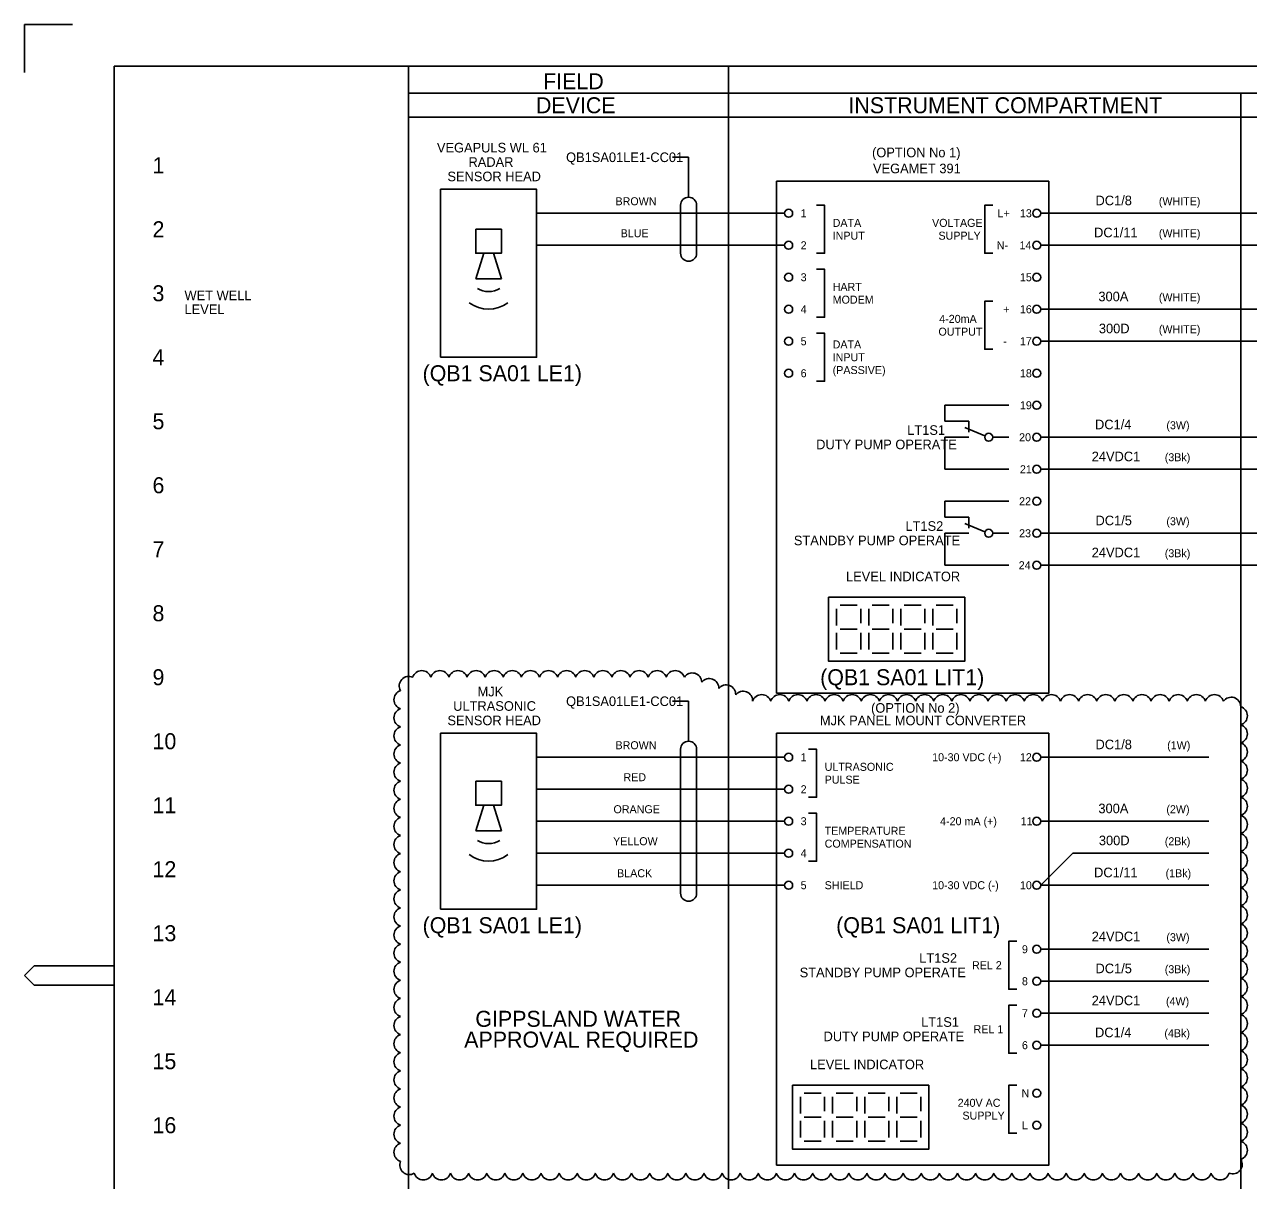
# Model space of a CAD drawing. Extents: x 0 to 841, y 0 to 594.
# Drawn here: x 0 to 382.4, y 232.7 to 594 of the extents above; entities that cross this region are included whole.
import ezdxf

# ---------------------------------------------------------------- set-up
doc = ezdxf.new("R2010")
doc.units = 0
for name, color, linetype in [('A1BORDER', 7, 'Continuous'), ('BASE', 7, 'Continuous'), ('Level 1', 7, 'Continuous'), ('Level 10', 7, 'Continuous'), ('Level 2', 7, 'Continuous'), ('Level 3', 7, 'Continuous')]:
    doc.layers.add(name, color=color, linetype=linetype)

msp = doc.modelspace()

# ---------------------------------------------------------------- linework, layer by layer
at = {"layer": 'A1BORDER'}
for p, q in [((0, 594), (15, 594)), ((0, 579), (0, 594)), ((28, 581), (829, 581)), ((28, 581), (28, 15)), ((3, 299.76), (0, 296.76)), ((28, 299.76), (3, 299.76)), ((3, 293.76), (0, 296.76)), ((28, 293.76), (3, 293.76))]:
    msp.add_line(p, q, dxfattribs=at)
at = {"layer": 'BASE'}
for p, q in [((317.5, 535), (760, 535)), ((317.5, 525), (760, 525)), ((317.5, 505), (630, 505)), ((317.5, 495), (580, 495))]:
    msp.add_line(p, q, dxfattribs=at)
at = {"layer": 'Level 1'}
for p, q in [((120, 57.5), (120, 581)), ((220, 57.5), (220, 581)), ((120, 572.5), (829, 572.5)), ((380, 57), (380, 572.5)), ((120, 565), (829, 565)), ((207.5, 552.5), (202.5, 552.5)), ((207.5, 552.5), (207.5, 540)), ((205, 537.5), (205, 522.5)), ((210, 537.5), (210, 522.5)), ((237.5, 535), (160, 535)), ((237.5, 535), (237.5, 535)), ((240, 535), (240, 535)), ((315, 535), (315, 535)), ((317.5, 535), (317.5, 535)), ((237.5, 525), (160, 525)), ((237.5, 525), (237.5, 525)), ((240, 525), (240, 525)), ((315, 525), (315, 525)), ((317.5, 525), (317.5, 525)), ((237.5, 515), (237.5, 515)), ((240, 515), (240, 515)), ((315, 515), (315, 515)), ((317.5, 515), (317.5, 515)), ((237.5, 505), (237.5, 505)), ((240, 505), (240, 505)), ((315, 505), (315, 505)), ((317.5, 505), (317.5, 505)), ((237.5, 495), (237.5, 495)), ((240, 495), (240, 495)), ((315, 495), (315, 495)), ((317.5, 495), (317.5, 495)), ((237.5, 485), (237.5, 485)), ((240, 485), (240, 485)), ((315, 485), (315, 485)), ((317.5, 485), (317.5, 485)), ((287.5, 470), (287.5, 475)), ((287.5, 475), (307.5, 475)), ((315, 475), (315, 475)), ((317.5, 475), (317.5, 475)), ((287.5, 470), (292.5, 470)), ((287.5, 455), (287.5, 465)), ((287.5, 465), (292.5, 465)), ((292.5, 465), (292.5, 465)), ((302.5, 465), (302.5, 465)), ((302.5, 465), (307.5, 465)), ((315, 465), (315, 465)), ((317.5, 465), (317.5, 465)), ((760, 465), (317.5, 465)), ((307.5, 455), (287.5, 455)), ((315, 455), (315, 455)), ((317.5, 455), (317.5, 455)), ((760, 455), (317.5, 455)), ((287.5, 440), (287.5, 445)), ((287.5, 445), (307.5, 445)), ((315, 445), (315, 445)), ((317.5, 445), (317.5, 445)), ((287.5, 440), (292.5, 440)), ((287.5, 425), (287.5, 435)), ((287.5, 435), (292.5, 435)), ((292.5, 435), (292.5, 435)), ((302.5, 435), (302.5, 435)), ((302.5, 435), (307.5, 435)), ((315, 435), (315, 435)), ((317.5, 435), (317.5, 435)), ((760, 435), (317.5, 435)), ((307.5, 425), (287.5, 425)), ((315, 425), (315, 425)), ((317.5, 425), (317.5, 425)), ((760, 425), (317.5, 425)), ((207.5, 382.5), (202.5, 382.5)), ((207.5, 382.5), (207.5, 370)), ((205, 367.5), (205, 322.5)), ((210, 367.5), (210, 322.5)), ((237.5, 365), (160, 365)), ((237.5, 365), (237.5, 365)), ((240, 365), (240, 365)), ((315, 365), (315, 365)), ((317.5, 365), (317.5, 365)), ((370, 365), (317.5, 365)), ((237.5, 355), (160, 355)), ((237.5, 355), (237.5, 355)), ((240, 355), (240, 355)), ((237.5, 345), (160, 345)), ((237.5, 345), (237.5, 345)), ((240, 345), (240, 345)), ((315, 345), (315, 345)), ((317.5, 345), (317.5, 345)), ((370, 345), (317.5, 345)), ((237.5, 335), (160, 335)), ((237.5, 335), (237.5, 335)), ((240, 335), (240, 335)), ((317.5, 325), (327.5, 335)), ((370, 335), (327.5, 335)), ((237.5, 325), (160, 325)), ((237.5, 325), (237.5, 325)), ((240, 325), (240, 325)), ((315, 325), (315, 325)), ((317.5, 325), (317.5, 325)), ((370, 325), (317.5, 325)), ((315, 305), (315, 305)), ((317.5, 305), (317.5, 305)), ((370, 305), (317.5, 305)), ((315, 295), (315, 295)), ((317.5, 295), (317.5, 295)), ((370, 295), (317.5, 295)), ((315, 285), (315, 285)), ((317.5, 285), (317.5, 285)), ((370, 285), (317.5, 285)), ((315, 275), (315, 275)), ((317.5, 275), (317.5, 275)), ((370, 275), (317.5, 275)), ((315, 260), (315, 260)), ((317.5, 260), (317.5, 260)), ((315, 250), (315, 250)), ((317.5, 250), (317.5, 250))]:
    msp.add_line(p, q, dxfattribs=at)
for points in [[(235, 385), (235, 545), (320, 545), (320, 385)], [(130, 490), (130, 542.5), (160, 542.5), (160, 490)], [(251.25, 415), (293.75, 415), (293.75, 395), (251.25, 395)], [(130, 317.5), (130, 372.5), (160, 372.5), (160, 317.5)], [(235, 237.5), (235, 372.5), (320, 372.5), (320, 237.5)], [(240, 262.5), (282.5, 262.5), (282.5, 242.5), (240, 242.5)]]:
    msp.add_lwpolyline(points, close=True, dxfattribs=at)
for points in [[(247.5, 522.5), (250, 522.5), (250, 537.5), (247.5, 537.5)], [(302.5, 522.5), (300, 522.5), (300, 537.5), (302.5, 537.5)], [(247.5, 502.5), (250, 502.5), (250, 517.5), (247.5, 517.5)], [(302.5, 492.5), (300, 492.5), (300, 507.5), (302.5, 507.5)], [(247.5, 482.5), (250, 482.5), (250, 497.5), (247.5, 497.5)], [(245, 352.5), (247.5, 352.5), (247.5, 367.5), (245, 367.5)], [(245, 332.5), (247.5, 332.5), (247.5, 347.5), (245, 347.5)], [(310, 292.5), (307.5, 292.5), (307.5, 307.5), (310, 307.5)], [(310, 272.5), (307.5, 272.5), (307.5, 287.5), (310, 287.5)], [(310, 247.5), (307.5, 247.5), (307.5, 262.5), (310, 262.5)]]:
    msp.add_lwpolyline(points, dxfattribs=at)
for centre, radius, start, end in [((207.5, 537.5), 2.5, 0, 180), ((207.5, 522.5), 2.5, 180, 0), ((120.06, 387.3), 2.97, 65.3442, 210.3442), ((124.13, 389.11), 2.97, 17.5, 162.5), ((129.78, 389.11), 2.97, 17.5, 162.5), ((135.44, 389.11), 2.97, 17.5, 162.5), ((141.1, 389.11), 2.97, 17.5, 162.5), ((146.76, 389.11), 2.97, 17.5, 162.5), ((152.41, 389.11), 2.97, 17.5, 162.5), ((158.07, 389.11), 2.97, 17.5, 162.5), ((163.73, 389.11), 2.97, 17.5, 162.5), ((169.39, 389.11), 2.97, 17.5, 162.5), ((175.05, 389.11), 2.97, 17.5, 162.5), ((180.7, 389.11), 2.97, 17.5, 162.5), ((186.36, 389.11), 2.97, 17.5, 162.5), ((192.02, 389.11), 2.97, 17.5, 162.5), ((197.68, 389.11), 2.97, 17.5, 162.5), ((203.33, 389.11), 2.97, 17.5, 162.5), ((208.64, 388.37), 2.97, 1.7022, 146.7022), ((213.94, 386.63), 2.97, 356.944, 141.944), ((219.24, 384.64), 2.97, 356.944, 141.944), ((118.39, 382.98), 2.97, 107.5, 252.5), ((224.54, 382.66), 2.97, 356.944, 141.944), ((230.33, 381.61), 2.97, 17.5, 162.5), ((235.99, 381.61), 2.97, 17.5, 162.5), ((241.64, 381.61), 2.97, 17.5, 162.5), ((247.3, 381.61), 2.97, 17.5, 162.5), ((252.96, 381.61), 2.97, 17.5, 162.5), ((258.62, 381.61), 2.97, 17.5, 162.5), ((264.28, 381.61), 2.97, 17.5, 162.5), ((269.93, 381.61), 2.97, 17.5, 162.5), ((275.59, 381.61), 2.97, 17.5, 162.5), ((281.25, 381.61), 2.97, 17.5, 162.5), ((286.91, 381.61), 2.97, 17.5, 162.5), ((292.56, 381.61), 2.97, 17.5, 162.5), ((298.22, 381.61), 2.97, 17.5, 162.5), ((303.88, 381.61), 2.97, 17.5, 162.5), ((309.54, 381.61), 2.97, 17.5, 162.5), ((315.2, 381.61), 2.97, 17.5, 162.5), ((320.85, 381.61), 2.97, 17.5, 162.5), ((326.51, 381.61), 2.97, 17.5, 162.5), ((332.17, 381.61), 2.97, 17.5, 162.5), ((337.83, 381.61), 2.97, 17.5, 162.5), ((343.48, 381.61), 2.97, 17.5, 162.5), ((349.14, 381.61), 2.97, 17.5, 162.5), ((354.8, 381.61), 2.97, 17.5, 162.5), ((360.46, 381.61), 2.97, 17.5, 162.5), ((366.12, 381.61), 2.97, 17.5, 162.5), ((371.77, 381.61), 2.97, 17.5, 162.5), ((377.03, 380.79), 2.97, 359.904, 144.904), ((118.39, 377.32), 2.97, 107.5, 252.5), ((379.11, 377.96), 2.97, 287.5, 72.5), ((379.11, 372.3), 2.97, 287.5, 72.5), ((118.39, 371.66), 2.97, 107.5, 252.5), ((118.39, 366), 2.97, 107.5, 252.5), ((207.5, 367.5), 2.5, 0, 180), ((379.11, 366.64), 2.97, 287.5, 72.5), ((379.11, 360.98), 2.97, 287.5, 72.5), ((118.39, 360.35), 2.97, 107.5, 252.5), ((118.39, 354.69), 2.97, 107.5, 252.5), ((379.11, 355.33), 2.97, 287.5, 72.5), ((118.39, 349.03), 2.97, 107.5, 252.5), ((379.11, 349.67), 2.97, 287.5, 72.5), ((118.39, 343.37), 2.97, 107.5, 252.5), ((379.11, 344.01), 2.97, 287.5, 72.5), ((118.39, 337.72), 2.97, 107.5, 252.5), ((379.11, 338.35), 2.97, 287.5, 72.5), ((118.39, 332.06), 2.97, 107.5, 252.5), ((379.11, 332.7), 2.97, 287.5, 72.5), ((118.39, 326.4), 2.97, 107.5, 252.5), ((379.11, 327.04), 2.97, 287.5, 72.5), ((118.39, 320.74), 2.97, 107.5, 252.5), ((207.5, 322.5), 2.5, 180, 0), ((379.11, 321.38), 2.97, 287.5, 72.5), ((118.39, 315.08), 2.97, 107.5, 252.5), ((379.11, 315.72), 2.97, 287.5, 72.5), ((118.39, 309.43), 2.97, 107.5, 252.5), ((379.11, 310.06), 2.97, 287.5, 72.5), ((118.39, 303.77), 2.97, 107.5, 252.5), ((379.11, 304.41), 2.97, 287.5, 72.5), ((118.39, 298.11), 2.97, 107.5, 252.5), ((379.11, 298.75), 2.97, 287.5, 72.5), ((118.39, 292.45), 2.97, 107.5, 252.5), ((379.11, 293.09), 2.97, 287.5, 72.5), ((118.39, 286.8), 2.97, 107.5, 252.5), ((379.11, 287.43), 2.97, 287.5, 72.5), ((118.39, 281.14), 2.97, 107.5, 252.5), ((379.11, 281.78), 2.97, 287.5, 72.5), ((118.39, 275.48), 2.97, 107.5, 252.5), ((379.11, 276.12), 2.97, 287.5, 72.5), ((118.39, 269.82), 2.97, 107.5, 252.5), ((379.11, 270.46), 2.97, 287.5, 72.5), ((118.39, 264.16), 2.97, 107.5, 252.5), ((379.11, 264.8), 2.97, 287.5, 72.5), ((118.39, 258.51), 2.97, 107.5, 252.5), ((379.11, 259.14), 2.97, 287.5, 72.5), ((379.11, 253.49), 2.97, 287.5, 72.5), ((118.39, 252.85), 2.97, 107.5, 252.5), ((118.39, 247.19), 2.97, 107.5, 252.5), ((379.11, 247.83), 2.97, 287.5, 72.5), ((379.11, 242.17), 2.97, 287.5, 72.5), ((118.39, 241.53), 2.97, 107.5, 252.5), ((120.22, 237.53), 2.97, 156.6035, 301.6035), ((377.5, 237.74), 2.96, 247.6624, 32.6624), ((124.61, 235.89), 2.97, 197.5, 342.5), ((130.26, 235.89), 2.97, 197.5, 342.5), ((135.92, 235.89), 2.97, 197.5, 342.5), ((141.58, 235.89), 2.97, 197.5, 342.5), ((147.24, 235.89), 2.97, 197.5, 342.5), ((152.89, 235.89), 2.97, 197.5, 342.5), ((158.55, 235.89), 2.97, 197.5, 342.5), ((164.21, 235.89), 2.97, 197.5, 342.5), ((169.87, 235.89), 2.97, 197.5, 342.5), ((175.53, 235.89), 2.97, 197.5, 342.5), ((181.18, 235.89), 2.97, 197.5, 342.5), ((186.84, 235.89), 2.97, 197.5, 342.5), ((192.5, 235.89), 2.97, 197.5, 342.5), ((198.16, 235.89), 2.97, 197.5, 342.5), ((203.81, 235.89), 2.97, 197.5, 342.5), ((209.47, 235.89), 2.97, 197.5, 342.5), ((215.13, 235.89), 2.97, 197.5, 342.5), ((220.79, 235.89), 2.97, 197.5, 342.5), ((226.45, 235.89), 2.97, 197.5, 342.5), ((232.1, 235.89), 2.97, 197.5, 342.5), ((237.76, 235.89), 2.97, 197.5, 342.5), ((243.42, 235.89), 2.97, 197.5, 342.5), ((249.08, 235.89), 2.97, 197.5, 342.5), ((254.73, 235.89), 2.97, 197.5, 342.5), ((260.39, 235.89), 2.97, 197.5, 342.5), ((266.05, 235.89), 2.97, 197.5, 342.5), ((271.71, 235.89), 2.97, 197.5, 342.5), ((277.36, 235.89), 2.97, 197.5, 342.5), ((283.02, 235.89), 2.97, 197.5, 342.5), ((288.68, 235.89), 2.97, 197.5, 342.5), ((294.34, 235.89), 2.97, 197.5, 342.5), ((300, 235.89), 2.97, 197.5, 342.5), ((305.65, 235.89), 2.97, 197.5, 342.5), ((311.31, 235.89), 2.97, 197.5, 342.5), ((316.97, 235.89), 2.97, 197.5, 342.5), ((322.63, 235.89), 2.97, 197.5, 342.5), ((328.28, 235.89), 2.97, 197.5, 342.5), ((333.94, 235.89), 2.97, 197.5, 342.5), ((339.6, 235.89), 2.97, 197.5, 342.5), ((345.26, 235.89), 2.97, 197.5, 342.5), ((350.92, 235.89), 2.97, 197.5, 342.5), ((356.57, 235.89), 2.97, 197.5, 342.5), ((362.23, 235.89), 2.97, 197.5, 342.5), ((367.89, 235.89), 2.97, 197.5, 342.5), ((373.55, 235.89), 2.97, 197.5, 342.5)]:
    msp.add_arc(centre, radius, start, end, dxfattribs=at)
at = {"layer": 'Level 10'}
for p, q in [((295, 470), (292.5, 470)), ((300.09, 465.46), (293.75, 468)), ((295, 466.63), (295, 470)), ((295, 465), (292.5, 465)), ((295, 440), (292.5, 440)), ((295, 436.63), (295, 440)), ((300.09, 435.46), (293.75, 438)), ((295, 435), (292.5, 435))]:
    msp.add_line(p, q, dxfattribs=at)
for centre in [(238.75, 535), (316.25, 535), (238.75, 525), (316.25, 525), (238.75, 515), (316.25, 515), (238.75, 505), (316.25, 505), (238.75, 495), (316.25, 495), (238.75, 485), (316.25, 485), (316.25, 475), (301.25, 465), (316.25, 465), (316.25, 455), (316.25, 445), (301.25, 435), (316.25, 435), (316.25, 425), (238.75, 365), (316.25, 365), (238.75, 355), (238.75, 345), (316.25, 345), (238.75, 335), (238.75, 325), (316.25, 325), (316.25, 305), (316.25, 295), (316.25, 285), (316.25, 275), (316.25, 260), (316.25, 250)]:
    msp.add_circle(centre, 1.25, dxfattribs=at)
at = {"layer": 'Level 2'}
for p, q in [((253.75, 411.38), (253.75, 406.13)), ((254.88, 412.5), (260.12, 412.5)), ((261.25, 411.38), (261.25, 406.88)), ((263.75, 411.38), (263.75, 406.13)), ((264.88, 412.5), (270.12, 412.5)), ((271.25, 411.38), (271.25, 406.88)), ((273.75, 411.38), (273.75, 406.13)), ((274.88, 412.5), (280.12, 412.5)), ((281.25, 411.38), (281.25, 406.88)), ((283.75, 411.38), (283.75, 406.13)), ((284.88, 412.5), (290.12, 412.5)), ((291.25, 411.38), (291.25, 406.88)), ((253.75, 403.88), (253.75, 398.63)), ((254.88, 405), (260.12, 405)), ((261.25, 403.88), (261.25, 398.63)), ((263.75, 403.88), (263.75, 398.63)), ((264.88, 405), (270.12, 405)), ((271.25, 403.88), (271.25, 398.63)), ((273.75, 403.88), (273.75, 398.63)), ((274.88, 405), (280.12, 405)), ((281.25, 403.88), (281.25, 398.63)), ((283.75, 403.88), (283.75, 398.63)), ((284.88, 405), (290.12, 405)), ((291.25, 403.88), (291.25, 398.63)), ((254.88, 397.5), (260.12, 397.5)), ((264.88, 397.5), (270.12, 397.5)), ((274.88, 397.5), (280.12, 397.5)), ((284.88, 397.5), (290.12, 397.5)), ((242.5, 258.88), (242.5, 253.63)), ((243.63, 260), (248.87, 260)), ((250, 258.88), (250, 254.38)), ((252.5, 258.88), (252.5, 253.63)), ((253.63, 260), (258.87, 260)), ((260, 258.88), (260, 254.38)), ((262.5, 258.88), (262.5, 253.63)), ((263.63, 260), (268.87, 260)), ((270, 258.88), (270, 254.38)), ((272.5, 258.88), (272.5, 253.63)), ((273.63, 260), (278.87, 260)), ((280, 258.88), (280, 254.38)), ((243.63, 252.5), (248.87, 252.5)), ((253.63, 252.5), (258.87, 252.5)), ((263.63, 252.5), (268.87, 252.5)), ((273.63, 252.5), (278.87, 252.5)), ((242.5, 251.38), (242.5, 246.13)), ((250, 251.38), (250, 246.13)), ((252.5, 251.38), (252.5, 246.13)), ((260, 251.38), (260, 246.13)), ((262.5, 251.38), (262.5, 246.13)), ((270, 251.38), (270, 246.13)), ((272.5, 251.38), (272.5, 246.13)), ((280, 251.38), (280, 246.13)), ((243.63, 245), (248.87, 245)), ((253.63, 245), (258.87, 245)), ((263.63, 245), (268.87, 245)), ((273.63, 245), (278.87, 245))]:
    msp.add_line(p, q, dxfattribs=at)
at = {"layer": 'Level 3'}
for p, q in [((143.5, 522.5), (141, 514.5)), ((149, 514.5), (146.5, 522.5)), ((141, 514.5), (149, 514.5)), ((143.5, 350), (141, 342)), ((149, 342), (146.5, 350)), ((141, 342), (149, 342))]:
    msp.add_line(p, q, dxfattribs=at)
for points in [[(141, 530), (149, 530), (149, 522.5), (141, 522.5)], [(141, 357.5), (149, 357.5), (149, 350), (141, 350)]]:
    msp.add_lwpolyline(points, close=True, dxfattribs=at)
for centre, radius, start, end in [((145, 517.11), 6.61, 237.9927, 301.9255), ((145, 514.83), 9.83, 232.2557, 307.7162), ((145, 344.61), 6.61, 237.9927, 301.9255), ((145, 342.33), 9.83, 232.2557, 307.7162)]:
    msp.add_arc(centre, radius, start, end, dxfattribs=at)

# ---------------------------------------------------------------- texts
at = {"layer": 'Level 1'}
for s, height, p in [('FIELD', 5, (162.03, 573.75)), ('DEVICE', 5, (159.79, 566.25)), ('INSTRUMENT COMPARTMENT', 5, (257.42, 566.25)), ('VEGAPULS WL 61', 3, (128.86, 554.01)), ('(OPTION No 1)', 3, (264.8, 552.5)), ('1', 5, (40, 547.5)), ('RADAR', 3, (138.72, 549.51)), ('QB1SA01LE1-CC01', 3, (169.22, 551)), ('SENSOR HEAD', 3, (132.15, 545.01)), ('VEGAMET 391', 3, (265.1, 547.5)), ('BROWN', 2.5, (184.65, 537.5)), ('DC1/8', 3, (334.62, 537.5)), ('(WHITE)', 2.5, (354.4, 537.5)), ('1', 2.5, (242.5, 533.75)), ('L+', 2.5, (304.01, 533.75)), ('13', 2.5, (311, 533.75)), ('2', 5, (40, 527.5)), ('DATA', 2.5, (252.5, 530.75)), ('VOLTAGE', 2.5, (283.55, 530.75)), ('BLUE', 2.5, (186.26, 527.5)), ('INPUT', 2.5, (252.5, 526.75)), ('SUPPLY', 2.5, (285.55, 526.75)), ('DC1/11', 3, (334.17, 527.5)), ('(WHITE)', 2.5, (354.4, 527.5)), ('2', 2.5, (242.5, 523.75)), ('N-', 2.5, (303.76, 523.75)), ('14', 2.5, (310.88, 523.75)), ('3', 2.5, (242.5, 513.75)), ('3', 5, (40, 507.5)), ('HART', 2.5, (252.5, 510.75)), ('15', 2.5, (311, 513.75)), ('WET WELL', 3, (50, 507.84)), ('MODEM', 2.5, (252.5, 506.75)), ('300A', 3, (335.52, 507.5)), ('(WHITE)', 2.5, (354.4, 507.5)), ('LEVEL', 3, (50, 503.5)), ('4', 2.5, (242.5, 503.75)), ('+', 2.5, (305.76, 503.75)), ('16', 2.5, (311, 503.75)), ('4-20mA', 2.5, (285.79, 500.75)), ('OUTPUT', 2.5, (285.55, 496.75)), ('300D', 3, (335.67, 497.5)), ('(WHITE)', 2.5, (354.4, 497.5)), ('5', 2.5, (242.5, 493.75)), ('DATA', 2.5, (252.5, 492.75)), ('-', 2.5, (305.76, 493.75)), ('17', 2.5, (311, 493.75)), ('4', 5, (40, 487.5)), ('INPUT', 2.5, (252.5, 488.75)), ('(QB1 SA01 LE1)', 5, (124.38, 482.5)), ('6', 2.5, (242.5, 483.75)), ('(PASSIVE)', 2.5, (252.5, 484.75)), ('18', 2.5, (311, 483.75)), ('19', 2.5, (311, 473.75)), ('5', 5, (40, 467.5)), ('DC1/4', 3, (334.47, 467.5)), ('LT1S1', 3, (275.8, 465.75)), ('(3W)', 2.5, (356.76, 467.5)), ('DUTY PUMP OPERATE', 3, (247.35, 461.25)), ('20', 2.5, (310.75, 463.75)), ('24VDC1', 3, (333.43, 457.5)), ('(3Bk)', 2.5, (356.26, 457.5)), ('21', 2.5, (311, 453.75)), ('6', 5, (40, 447.5)), ('22', 2.5, (310.75, 443.75)), ('DC1/5', 3, (334.62, 437.5)), ('(3W)', 2.5, (356.76, 437.5)), ('LT1S2', 3, (275.24, 435.75)), ('23', 2.5, (310.75, 433.75)), ('7', 5, (40, 427.5)), ('STANDBY PUMP OPERATE', 3, (240.37, 431.25)), ('24VDC1', 3, (333.43, 427.5)), ('(3Bk)', 2.5, (356.26, 427.5)), ('24', 2.5, (310.63, 423.75)), ('8', 5, (40, 407.5)), ('9', 5, (40, 387.5)), ('(QB1 SA01 LIT1)', 5, (248.59, 387.5)), ('MJK', 3, (141.56, 384.01)), ('ULTRASONIC', 3, (133.94, 379.51)), ('QB1SA01LE1-CC01', 3, (169.22, 381)), ('(OPTION No 2)', 3, (264.5, 378.9)), ('SENSOR HEAD', 3, (132.15, 375.01)), ('MJK PANEL MOUNT CONVERTER', 3, (248.51, 375)), ('10', 5, (40, 367.5)), ('BROWN', 2.5, (184.65, 367.5)), ('DC1/8', 3, (334.62, 367.5)), ('(1W)', 2.5, (357.01, 367.5)), ('1', 2.5, (242.5, 363.75)), ('10-30 VDC (+)', 2.5, (283.58, 363.75)), ('12', 2.5, (311, 363.75)), ('RED', 2.5, (187.14, 357.5)), ('ULTRASONIC', 2.5, (250, 360.75)), ('2', 2.5, (242.5, 353.75)), ('PULSE', 2.5, (250, 356.75)), ('11', 5, (40, 347.5)), ('ORANGE', 2.5, (184.02, 347.5)), ('300A', 3, (335.52, 347.5)), ('(2W)', 2.5, (356.76, 347.5)), ('3', 2.5, (242.5, 343.75)), ('4-20 mA (+)', 2.5, (286.07, 343.75)), ('11', 2.5, (311.25, 343.75)), ('TEMPERATURE', 2.5, (250, 340.75)), ('300D', 3, (335.67, 337.5)), ('YELLOW', 2.5, (183.9, 337.5)), ('COMPENSATION', 2.5, (250, 336.75)), ('(2Bk)', 2.5, (356.26, 337.5)), ('4', 2.5, (242.5, 333.75)), ('12', 5, (40, 327.5)), ('BLACK', 2.5, (185.14, 327.5)), ('DC1/11', 3, (334.17, 327.5)), ('(1Bk)', 2.5, (356.51, 327.5)), ('5', 2.5, (242.5, 323.75)), ('SHIELD', 2.5, (250, 323.75)), ('10-30 VDC (-)', 2.5, (283.58, 323.75)), ('10', 2.5, (311, 323.75)), ('(QB1 SA01 LE1)', 5, (124.38, 310)), ('(QB1 SA01 LIT1)', 5, (253.59, 310)), ('13', 5, (40, 307.5)), ('24VDC1', 3, (333.43, 307.5)), ('(3W)', 2.5, (356.76, 307.5)), ('9', 2.5, (311.63, 303.75)), ('LT1S2', 3, (279.54, 300.75)), ('STANDBY PUMP OPERATE', 3, (242.19, 296.25)), ('REL 2', 2.5, (296.03, 298.75)), ('DC1/5', 3, (334.62, 297.5)), ('(3Bk)', 2.5, (356.26, 297.5)), ('8', 2.5, (311.63, 293.75)), ('14', 5, (40, 287.5)), ('24VDC1', 3, (333.43, 287.5)), ('(4W)', 2.5, (356.64, 287.5)), ('GIPPSLAND WATER', 5, (140.86, 280.75)), ('LT1S1', 3, (280.14, 280.75)), ('7', 2.5, (311.63, 283.75)), ('APPROVAL REQUIRED', 5, (137.38, 274.25)), ('DUTY PUMP OPERATE', 3, (249.66, 276.25)), ('REL 1', 2.5, (296.53, 278.75)), ('DC1/4', 3, (334.47, 277.5)), ('(4Bk)', 2.5, (356.14, 277.5)), ('6', 2.5, (311.63, 273.75)), ('15', 5, (40, 267.5)), ('N', 2.5, (311.5, 258.75)), ('240V AC', 2.5, (291.55, 255.75)), ('16', 5, (40, 247.5)), ('SUPPLY', 2.5, (293.05, 251.75)), ('L', 2.5, (311.63, 248.75))]:
    msp.add_text(s, height=height, dxfattribs=at).set_placement(p)
at = {"layer": 'Level 2'}
for p in [(256.66, 420), (245.41, 267.5)]:
    msp.add_text('LEVEL INDICATOR', height=3, dxfattribs=at).set_placement(p)

doc.saveas('drawing.dxf')
